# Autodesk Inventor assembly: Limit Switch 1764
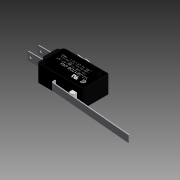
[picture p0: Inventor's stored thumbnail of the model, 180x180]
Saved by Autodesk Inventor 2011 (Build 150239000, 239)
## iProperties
Shininess: 0.0
Created: 2002-01
Part Number: Limit Switch 1764
Document SubType Name: Assembly
Density: 0.0
Volumn: 0.0
Area: 0.0
PropertySet Name: Model Information
Control State: 0
Master: False
Checked Out: False
Author: Administrator
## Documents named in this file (6)
- R:\CAD Archives\Electronics\Limitswitch 1764\Limit Switch 1764.iam
- R:\CAD Archives\Electronics\Limitswitch 1764\COM 1764.ipt
- R:\CAD Archives\Electronics\Limitswitch 1764\Limit Switch Part 3 1764.ipt
- R:\CAD Archives\Electronics\Limitswitch 1764\Limit Switch Part 6 1764.ipt
- R:\CAD Archives\Electronics\Limitswitch 1764\Limit Switch Part 1 1764.ipt
- R:\CAD Archives\Electronics\Limitswitch 1764\Limit Switch Part 4 1764.ipt
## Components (6 placed, 5 different names)
1. Limit Switch Part 3 1764:1 — Mate:3, Flush:6, Flush:7, Flush:8
2. Limit Switch Part 6 1764:1 — Flush:5, Mate:3, Flush:6, Flush:7, Mate:5, Flush:9, Mate:6, Mate:7, Flush:11, Mate:8
3. COM 1764:1 — Flush:5
4. Limit Switch Part 1 1764:1 — Flush:8, Mate:5, Flush:9
5. Limit Switch Part 4 1764:1 — Flush:10, Mate:6, Flush:12, Mate:8
6. Limit Switch Part 4 1764:2 — Flush:10, Mate:7, Flush:11, Flush:12
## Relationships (13: Flush 8, Mate 5)
- Flush:5: Limit Switch Part 6 1764:1 ↔ COM 1764:1
- Mate:3: Limit Switch Part 3 1764:1 ↔ Limit Switch Part 6 1764:1
- Flush:6: Limit Switch Part 3 1764:1 ↔ Limit Switch Part 6 1764:1
- Flush:7: Limit Switch Part 3 1764:1 ↔ Limit Switch Part 6 1764:1
- Flush:8: Limit Switch Part 3 1764:1 ↔ Limit Switch Part 1 1764:1
- Mate:5: Limit Switch Part 6 1764:1 ↔ Limit Switch Part 1 1764:1
- Flush:9: Limit Switch Part 6 1764:1 ↔ Limit Switch Part 1 1764:1
- Flush:10: Limit Switch Part 4 1764:1 ↔ Limit Switch Part 4 1764:2
- Mate:6: Limit Switch Part 6 1764:1 ↔ Limit Switch Part 4 1764:1
- Mate:7: Limit Switch Part 6 1764:1 ↔ Limit Switch Part 4 1764:2
- Flush:11: Limit Switch Part 6 1764:1 ↔ Limit Switch Part 4 1764:2
- Flush:12: Limit Switch Part 4 1764:1 ↔ Limit Switch Part 4 1764:2
- Mate:8: Limit Switch Part 6 1764:1 ↔ Limit Switch Part 4 1764:1
